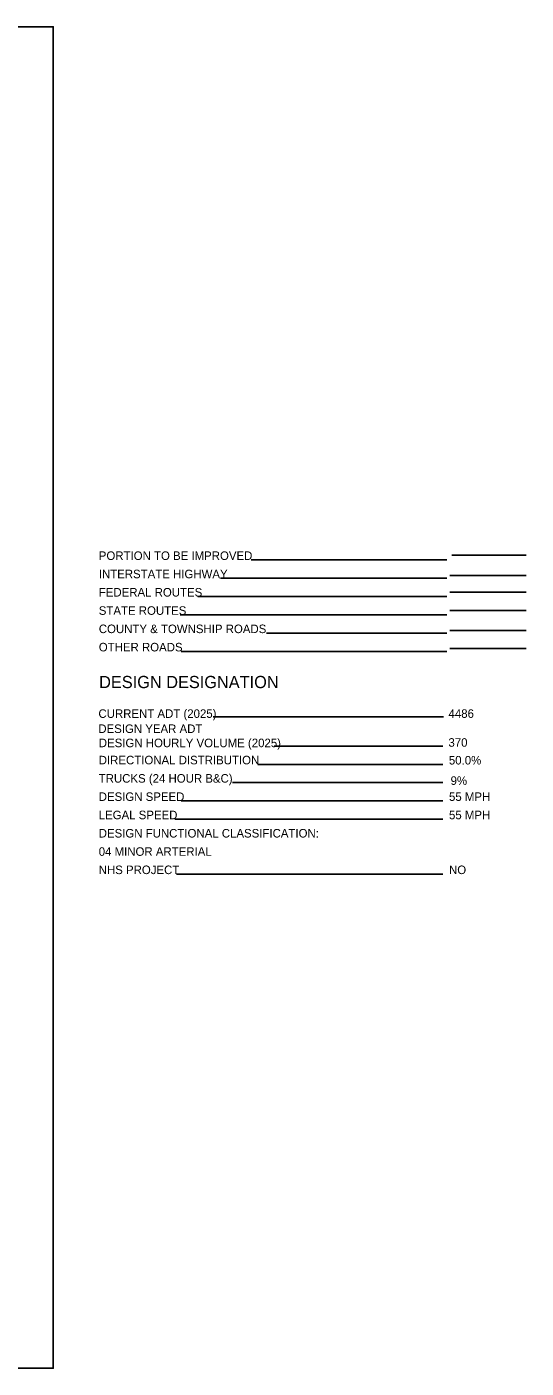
# Model space of a CAD drawing. Extents: x -139 to 835, y 0 to 440.
# Drawn here: x 671.4 to 835.1, y 0 to 440 of the extents above; entities that cross this region are included whole.
import ezdxf

# ---------------------------------------------------------------- set-up
doc = ezdxf.new("R2010")
doc.units = 0
for name, color, linetype in [('Default', 7, 'Continuous'), ('SH_Cut_Line', 7, 'Continuous'), ('SH_Data', 7, 'Continuous'), ('SH_Text', 7, 'Continuous')]:
    doc.layers.add(name, color=color, linetype=linetype)

msp = doc.modelspace()

# ---------------------------------------------------------------- linework, layer by layer
at = {"layer": 'SH_Cut_Line'}
msp.add_lwpolyline([(0, 0), (680, 0), (680, 440), (0, 440)], close=True, dxfattribs=at)
at = {"layer": 'SH_Data'}
for p, q in [((809.06, 265.12), (744.94, 265.12)), ((810.72, 266.69), (835.06, 266.69)), ((835.06, 260), (810.06, 260)), ((809.06, 259.12), (734.85, 259.12)), ((809.06, 253.12), (727.45, 253.12)), ((835.06, 254.57), (810.06, 254.57)), ((809.06, 247.12), (721.64, 247.12)), ((835.06, 248.57), (810.06, 248.57)), ((835.06, 242.03), (810.06, 242.03)), ((809.06, 241.12), (749.97, 241.12)), ((809.06, 235.12), (722, 235.12)), ((835.06, 236.03), (810.06, 236.03)), ((807.91, 213.71), (732.48, 213.71)), ((807.77, 204.07), (752.48, 204.07)), ((807.77, 198.07), (747.11, 198.07)), ((807.77, 192.07), (738.8, 192.07)), ((807.77, 186.07), (721.95, 186.07)), ((807.77, 180.07), (719.88, 180.07)), ((807.77, 162.07), (720.37, 162.07))]:
    msp.add_line(p, q, dxfattribs=at)

# ---------------------------------------------------------------- texts
at = {"layer": 'Default'}
for s, p in [('CURRENT ADT (2025)', (694.83, 213.32)), ('4486', (809.61, 213.32)), ('DESIGN YEAR ADT                    ', (694.79, 208.36)), ('DESIGN HOURLY VOLUME (2025)', (694.95, 203.7)), ('370', (809.58, 203.85)), ('50.0%', (809.73, 198.02)), ('9%', (810.28, 191.33))]:
    msp.add_text(s, height=2.8, dxfattribs=at).set_placement(p)
at = {"layer": 'SH_Data'}
msp.add_text('DESIGN DESIGNATION', height=4, dxfattribs=at).set_placement((695.06, 223.08))
at = {"layer": 'SH_Text'}
for s, p in [('PORTION TO BE IMPROVED', (694.95, 265.12)), ('INTERSTATE HIGHWAY', (694.95, 259.12)), ('FEDERAL ROUTES', (694.95, 253.12)), ('STATE ROUTES', (694.95, 247.12)), ('COUNTY & TOWNSHIP ROADS', (694.95, 241.12)), ('OTHER ROADS', (694.95, 235.12)), ('DIRECTIONAL DISTRIBUTION', (694.92, 198.07)), ('TRUCKS (24 HOUR B&C)', (694.92, 192.07)), ('DESIGN SPEED', (694.92, 186.07)), ('55 MPH', (809.77, 186.07)), ('LEGAL SPEED', (694.92, 180.07)), ('55 MPH', (809.77, 180.07)), ('DESIGN FUNCTIONAL CLASSIFICATION:', (694.92, 174.07)), ('04 MINOR ARTERIAL', (694.92, 168.07)), ('NHS PROJECT', (694.92, 162.07)), ('NO', (809.77, 162.07))]:
    msp.add_text(s, height=2.8, dxfattribs=at).set_placement(p)

doc.saveas('drawing.dxf')
